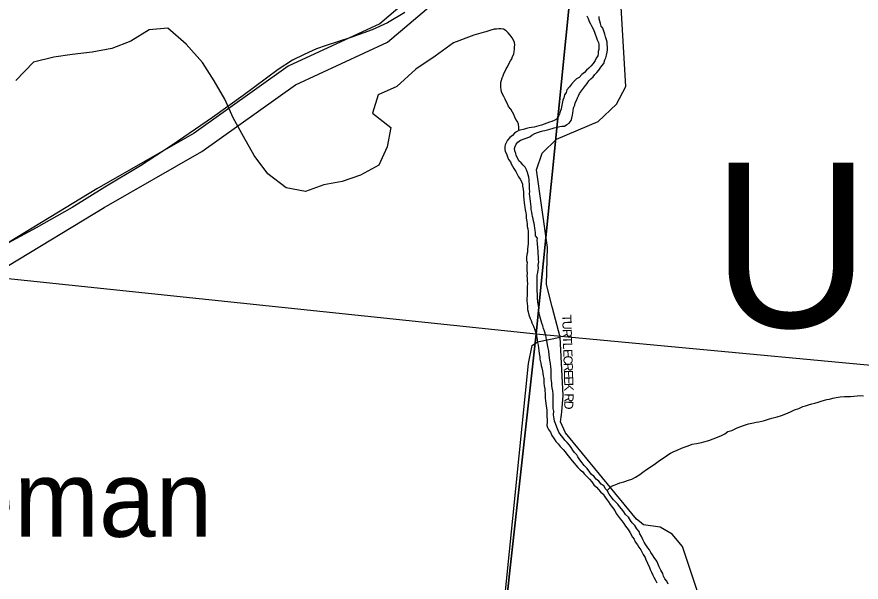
# Model space of a CAD drawing. Extents: x 0 to 34, y -4 to 22.
# Drawn here: x 3.906 to 4.522, y 18.618 to 19.03 of the extents above; entities that cross this region are included whole.
import ezdxf

# ---------------------------------------------------------------- set-up
doc = ezdxf.new("R2010")
doc.units = 0
for name, color, linetype in [('GM_X_City_Street', 7, 'Continuous'), ('GM_X_City_Street_Text', 7, 'Continuous'), ('GM_X_Corporation', 7, 'Continuous'), ('GM_X_County_Road', 7, 'Continuous'), ('GM_X_Minor_River', 7, 'Continuous'), ('GM_X_Rail_Line', 7, 'Continuous'), ('GM_X_Section', 7, 'Continuous'), ('GM_X_Township_Road', 7, 'Continuous'), ('GM_X_Township_Text', 7, 'Continuous'), ('GM_X_Unincorporated_Text', 7, 'Continuous')]:
    doc.layers.add(name, color=color, linetype=linetype)

msp = doc.modelspace()

# ---------------------------------------------------------------- linework, layer by layer
at = {"layer": 'GM_X_City_Street'}
msp.add_lwpolyline([(4.30361, 18.74044), (4.30384, 18.74223), (4.30486, 18.75426), (4.30269, 18.7967)], dxfattribs=at)
at = {"layer": 'GM_X_Corporation'}
msp.add_lwpolyline([(3.90028, 18.84891), (3.97005, 18.89124), (4.04146, 18.932), (4.10968, 18.98061), (4.17685, 19.01173), (4.24489, 19.06965), (4.32583, 19.18677), (4.35455, 19.22188), (4.40569, 19.29705), (4.44231, 19.37455), (4.44713, 19.39206), (4.42391, 19.39206), (4.42052, 19.37907), (4.38533, 19.3024), (4.33505, 19.23202), (4.30739, 19.18845), (4.23841, 19.08244), (4.1712, 19.02523), (4.10434, 18.99426), (4.03585, 18.94545), (3.96469, 18.90484), (3.89508, 18.8626)], dxfattribs=at)
at = {"layer": 'GM_X_County_Road'}
for points in [[(4.30269, 18.7967), (4.29682, 18.81893), (4.29278, 18.83509), (4.29361, 18.86203), (4.28538, 18.9188), (4.28964, 18.93093), (4.29997, 18.94102), (4.33049, 18.95404), (4.34395, 18.96661), (4.35069, 18.9794), (4.34148, 19.13651), (4.33767, 19.16075), (4.33946, 19.17084), (4.3637, 19.18566), (4.38098, 19.19217), (4.40769, 19.19845), (4.42161, 19.2099), (4.43485, 19.23009), (4.47033, 19.29782), (4.51074, 19.39206)], [(4.24504, 18.43619), (4.27961, 18.77764), (4.28221, 18.79071), (4.28627, 18.79333), (4.30269, 18.7967)]]:
    msp.add_lwpolyline(points, dxfattribs=at)
at = {"layer": 'GM_X_Minor_River'}
for points in [[(4.32228, 19.03111), (4.32328, 19.02895), (4.32401, 19.02679), (4.32476, 19.02516), (4.32577, 19.02326), (4.32679, 19.02163), (4.32778, 19.01919), (4.32826, 19.01757), (4.329, 19.01568), (4.32973, 19.01352), (4.33074, 19.01162), (4.33096, 19.01001), (4.3309, 19.00814), (4.33084, 19.00654), (4.33052, 19.00495), (4.33047, 19.00335), (4.33015, 19.00175), (4.32903, 19.00019), (4.32816, 18.99834), (4.32675, 18.99625), (4.32509, 18.99443), (4.32369, 18.99287), (4.32204, 18.99132), (4.32038, 18.98977), (4.31845, 18.98822), (4.31651, 18.98615), (4.3146, 18.98514), (4.31293, 18.98332), (4.31099, 18.98124), (4.30958, 18.97915), (4.30763, 18.97707), (4.30704, 18.97522), (4.3059, 18.97338), (4.3053, 18.97127), (4.3047, 18.96942), (4.30409, 18.96703), (4.30374, 18.96464), (4.30342, 18.96304), (4.30282, 18.96119), (4.30222, 18.95934), (4.30164, 18.95776), (4.29996, 18.95567), (4.29832, 18.95465), (4.29669, 18.9539), (4.29506, 18.95342), (4.2929, 18.95268), (4.291, 18.95194), (4.2891, 18.9512), (4.2872, 18.95072), (4.28558, 18.95024), (4.28369, 18.94976), (4.28181, 18.94955), (4.28019, 18.94934), (4.2783, 18.94886), (4.27668, 18.94838), (4.27263, 18.94743)], [(4.27374, 18.94045), (4.28052, 18.94291), (4.28216, 18.94393), (4.28434, 18.9452), (4.28624, 18.94594), (4.28841, 18.94668), (4.29003, 18.94716), (4.29165, 18.94738), (4.29354, 18.94785), (4.29516, 18.94834), (4.29679, 18.94882), (4.29841, 18.94931), (4.30057, 18.94977), (4.30246, 18.95025), (4.30407, 18.95047), (4.30596, 18.95068), (4.3076, 18.9517), (4.30924, 18.95271), (4.31065, 18.95481), (4.31124, 18.95639), (4.31184, 18.95851), (4.31189, 18.96011), (4.31222, 18.96197), (4.31255, 18.96383), (4.31343, 18.96594), (4.31375, 18.96753), (4.31461, 18.96938), (4.31548, 18.97122), (4.31607, 18.9728), (4.31692, 18.97438), (4.31832, 18.97621), (4.31973, 18.9783), (4.32113, 18.98013), (4.32252, 18.98169), (4.32365, 18.98352), (4.32504, 18.98508), (4.3267, 18.98663), (4.32809, 18.98819), (4.32948, 18.98975), (4.33087, 18.99131), (4.332, 18.99288), (4.33312, 18.99445), (4.33452, 18.99628), (4.33541, 18.99892), (4.336, 19.0005), (4.3366, 19.00236), (4.33694, 19.00448), (4.33727, 19.00634), (4.33734, 19.00848), (4.33712, 19.01009), (4.33691, 19.0117), (4.33643, 19.01358), (4.3357, 19.01574), (4.33523, 19.01762), (4.3345, 19.01978), (4.33376, 19.02194), (4.33275, 19.02358), (4.33227, 19.02546), (4.33179, 19.02708), (4.33131, 19.0287), (4.3311, 19.03058)], [(4.23983, 19.01683), (4.22501, 19.01136), (4.21153, 19.00172), (4.19738, 18.99209), (4.18349, 18.97951), (4.16988, 18.97335), (4.16587, 18.95997), (4.17922, 18.94953), (4.17655, 18.93561), (4.17041, 18.92223), (4.15706, 18.91474), (4.14371, 18.91019), (4.13036, 18.90778), (4.11701, 18.90296), (4.10286, 18.90564), (4.08951, 18.91581), (4.07963, 18.92919), (4.07162, 18.94311), (4.06415, 18.95676), (4.05801, 18.97014), (4.05027, 18.98353), (4.04173, 18.99691), (4.02998, 19.01029), (4.01663, 19.02207), (4.00301, 19.02073), (3.98966, 19.01243), (3.97578, 19.00708), (3.96136, 19.0044), (3.94668, 19.0028), (3.93333, 19.00092), (3.91865, 18.99718), (3.90556, 18.98379)], [(4.27263, 18.94743), (4.27271, 18.94983), (4.27224, 18.95198), (4.2715, 18.95388), (4.27049, 18.95551), (4.26973, 18.95714), (4.26899, 18.95903), (4.26798, 18.96066), (4.26671, 18.96284), (4.26517, 18.96502), (4.26443, 18.96692), (4.26341, 18.96855), (4.26266, 18.97018), (4.26166, 18.97208), (4.26065, 18.97398), (4.2599, 18.97561), (4.25968, 18.97722), (4.25947, 18.97883), (4.25953, 18.98069), (4.25958, 18.9823), (4.25991, 18.98415), (4.2605, 18.98574), (4.26109, 18.98732), (4.26168, 18.98891), (4.26254, 18.99075), (4.2634, 18.99233), (4.26425, 18.9939), (4.26539, 18.99601), (4.26653, 18.99811), (4.26739, 18.99968), (4.26798, 19.00127), (4.26884, 19.00311), (4.26917, 19.00497), (4.26949, 19.00656), (4.26955, 19.00817), (4.2696, 19.00977), (4.26939, 19.01164), (4.26864, 19.01327), (4.26763, 19.0149), (4.26635, 19.01681), (4.2648, 19.01873), (4.26324, 19.02012), (4.2614, 19.02124), (4.25954, 19.02156), (4.25793, 19.02161), (4.25632, 19.0214), (4.25471, 19.02118), (4.25227, 19.02045), (4.25065, 19.01997), (4.24848, 19.01924), (4.24659, 19.01876), (4.24497, 19.01828), (4.24307, 19.0178), (4.24145, 19.01732), (4.23983, 19.01683)], [(4.27263, 18.94743), (4.27099, 18.94641), (4.26935, 18.9454), (4.26795, 18.94384), (4.26603, 18.94229), (4.26436, 18.94047), (4.26351, 18.9389), (4.26264, 18.93705), (4.26232, 18.93546), (4.26227, 18.93386), (4.26274, 18.93198), (4.26349, 18.93035), (4.26422, 18.92819), (4.26496, 18.9263), (4.26652, 18.92465), (4.267, 18.92303), (4.26802, 18.9214), (4.26904, 18.91976), (4.2703, 18.91758), (4.27105, 18.91596), (4.27231, 18.91352), (4.2736, 18.91187), (4.27461, 18.91024), (4.27536, 18.90834), (4.2753, 18.90674), (4.27577, 18.90459), (4.27597, 18.90245), (4.27588, 18.89978), (4.27632, 18.8971), (4.27651, 18.89469), (4.27673, 18.89308), (4.27694, 18.89147), (4.27715, 18.88959)], [(4.2727, 18.92526), (4.27195, 18.92688), (4.27068, 18.92906), (4.27047, 18.93067), (4.26973, 18.93256), (4.26951, 18.93417), (4.26983, 18.93576), (4.27069, 18.93734), (4.27181, 18.93891), (4.27374, 18.94045)], [(4.30797, 18.71981), (4.30616, 18.72174), (4.30487, 18.72338), (4.30359, 18.72502), (4.3018, 18.72748), (4.3003, 18.731), (4.29932, 18.7337), (4.29858, 18.73559), (4.29837, 18.7372), (4.29793, 18.74015), (4.29802, 18.74282), (4.29754, 18.74471), (4.29762, 18.74711), (4.29768, 18.74898), (4.29775, 18.75111), (4.29756, 18.75326), (4.29762, 18.75512), (4.29743, 18.75753), (4.29697, 18.75968), (4.29676, 18.76156), (4.29655, 18.76317), (4.29633, 18.76478), (4.29613, 18.76692), (4.29622, 18.76959), (4.29627, 18.77119), (4.29606, 18.7728), (4.29587, 18.77521), (4.29568, 18.77762), (4.29523, 18.78004), (4.29481, 18.78353), (4.29438, 18.78674), (4.2939, 18.78863), (4.29345, 18.79105), (4.29324, 18.79292), (4.29278, 18.79508), (4.29234, 18.79803), (4.29137, 18.801), (4.29063, 18.80316), (4.29016, 18.80504), (4.28942, 18.80693), (4.28893, 18.80855), (4.28846, 18.81044), (4.28798, 18.81205), (4.28752, 18.8142), (4.2873, 18.81581), (4.28711, 18.81822), (4.2869, 18.81983), (4.28644, 18.82225), (4.28627, 18.8252), (4.2861, 18.82814), (4.2859, 18.83028), (4.28603, 18.83402), (4.28585, 18.8367), (4.28592, 18.83883), (4.28597, 18.84043), (4.28602, 18.84203), (4.28635, 18.84389), (4.28667, 18.84549), (4.28699, 18.84708), (4.2868, 18.84922), (4.28714, 18.85162), (4.28693, 18.85322), (4.287, 18.85536), (4.2868, 18.8575), (4.28659, 18.85911), (4.28641, 18.86179), (4.28625, 18.865), (4.28606, 18.86741), (4.28611, 18.86901), (4.28483, 18.87065), (4.28463, 18.8728), (4.28442, 18.87467), (4.28421, 18.87628), (4.284, 18.87816), (4.28379, 18.87977), (4.28331, 18.88139), (4.28309, 18.883), (4.28261, 18.88461), (4.28239, 18.88622), (4.28218, 18.88783), (4.28171, 18.88972), (4.28151, 18.89186), (4.2813, 18.89374), (4.2811, 18.89561), (4.2809, 18.89776), (4.28069, 18.89963), (4.28048, 18.90124), (4.28053, 18.90284), (4.28033, 18.90499), (4.2804, 18.90685), (4.28045, 18.90846), (4.28023, 18.91006), (4.28002, 18.91167), (4.27981, 18.91328), (4.27933, 18.91517), (4.27885, 18.91679), (4.27811, 18.91868), (4.2771, 18.92058), (4.27581, 18.92222), (4.27426, 18.92387), (4.2727, 18.92526)], [(4.27715, 18.88959), (4.27761, 18.88744), (4.27783, 18.88583), (4.27801, 18.88342), (4.27847, 18.881), (4.27868, 18.87913), (4.27862, 18.87752), (4.2791, 18.87564), (4.2793, 18.87376), (4.2795, 18.87162), (4.27944, 18.86975), (4.27935, 18.86708), (4.27928, 18.86495), (4.27921, 18.86281), (4.27889, 18.86122), (4.27881, 18.85882), (4.27848, 18.85696), (4.27814, 18.85483), (4.27807, 18.8527), (4.27855, 18.85108), (4.27849, 18.84921), (4.27843, 18.84734), (4.27838, 18.84574), (4.27856, 18.84307), (4.2785, 18.84146), (4.27872, 18.83986), (4.27865, 18.83772), (4.27885, 18.83584), (4.27877, 18.83344), (4.2787, 18.83131), (4.27863, 18.82917), (4.27855, 18.82677), (4.27849, 18.8249), (4.27843, 18.82303), (4.27864, 18.82142), (4.27883, 18.81902), (4.27903, 18.81687), (4.27951, 18.81525), (4.27998, 18.8131), (4.28096, 18.8104), (4.28171, 18.80877), (4.28219, 18.80716), (4.28318, 18.80472), (4.28417, 18.80202), (4.2849, 18.79986), (4.28536, 18.79771), (4.28608, 18.79502), (4.28627, 18.79287), (4.28675, 18.79099), (4.28694, 18.78884), (4.28715, 18.78697), (4.28735, 18.78483), (4.2878, 18.78241), (4.28802, 18.7808), (4.28873, 18.77784), (4.28893, 18.77596), (4.28941, 18.77434), (4.28988, 18.77219), (4.29008, 18.77032), (4.29029, 18.76844), (4.29076, 18.76656), (4.29071, 18.76495), (4.29092, 18.76308), (4.29112, 18.7612), (4.29159, 18.75905), (4.29153, 18.75745), (4.29175, 18.75584), (4.29169, 18.75397), (4.2919, 18.75236), (4.2921, 18.75022), (4.29231, 18.74861), (4.29251, 18.74647), (4.29296, 18.74378), (4.2929, 18.74191), (4.29311, 18.7403), (4.29306, 18.7387), (4.29326, 18.73683), (4.29319, 18.73469), (4.29312, 18.73256), (4.2936, 18.73094), (4.29435, 18.72931), (4.29563, 18.7274), (4.29662, 18.72497), (4.29842, 18.72251), (4.29969, 18.7206), (4.30125, 18.71895), (4.30279, 18.71703), (4.30486, 18.71483), (4.30641, 18.71318), (4.3077, 18.71154), (4.30949, 18.70908), (4.31155, 18.70661), (4.31284, 18.70496), (4.31412, 18.70332), (4.31568, 18.70167), (4.31723, 18.70002), (4.31933, 18.69862), (4.32035, 18.69699), (4.32242, 18.69479), (4.32424, 18.69313), (4.32578, 18.69121)], [(4.33709, 18.68498), (4.34014, 18.68809), (4.34204, 18.68884), (4.34449, 18.68983), (4.34639, 18.69057), (4.34909, 18.69129), (4.35261, 18.69252), (4.35505, 18.69324), (4.35778, 18.69476), (4.36078, 18.69654), (4.36299, 18.69834), (4.36573, 18.70013), (4.36902, 18.70243), (4.37231, 18.70473), (4.37422, 18.70601), (4.37669, 18.7078), (4.37943, 18.70959), (4.38135, 18.71086), (4.38327, 18.71214), (4.38518, 18.71315), (4.38817, 18.71439), (4.39116, 18.7159), (4.39387, 18.71689), (4.39604, 18.71762), (4.39902, 18.7186), (4.40226, 18.7193), (4.40576, 18.72), (4.40765, 18.72047), (4.41117, 18.72143), (4.41443, 18.72267), (4.41741, 18.72391), (4.4204, 18.72515), (4.42285, 18.72614), (4.42505, 18.72795), (4.42802, 18.72866), (4.42993, 18.72967), (4.43184, 18.73068), (4.43374, 18.73142), (4.43726, 18.73265), (4.44024, 18.73362), (4.44374, 18.73432), (4.44564, 18.73479), (4.44779, 18.73499), (4.44994, 18.73546), (4.45184, 18.73594), (4.45536, 18.73716), (4.45725, 18.73764), (4.45914, 18.73812), (4.46103, 18.73859), (4.46428, 18.73956), (4.46727, 18.7408), (4.4708, 18.7423), (4.4738, 18.74381), (4.47678, 18.74478), (4.47977, 18.74629), (4.48166, 18.74677), (4.48383, 18.7475), (4.48627, 18.74823), (4.48843, 18.7487), (4.49086, 18.74942), (4.49303, 18.75016), (4.49546, 18.75088), (4.49735, 18.75136), (4.49924, 18.75157), (4.50167, 18.7523), (4.5041, 18.75276), (4.50706, 18.7532), (4.51028, 18.75336), (4.5127, 18.75356), (4.51457, 18.7535), (4.51699, 18.75369), (4.51941, 18.75388), (4.52182, 18.75408), (4.52396, 18.75401)], [(4.38145, 18.61656), (4.38045, 18.61873), (4.37917, 18.62064), (4.37816, 18.62254), (4.37769, 18.62443), (4.37616, 18.62688), (4.37491, 18.62932), (4.37391, 18.63176), (4.37316, 18.63338), (4.37138, 18.63611), (4.3701, 18.63802), (4.36882, 18.63966), (4.36781, 18.64156), (4.36679, 18.64319), (4.36525, 18.64538), (4.36398, 18.64729), (4.36297, 18.64919), (4.36197, 18.65136), (4.36096, 18.65326), (4.36049, 18.65514), (4.35868, 18.65707), (4.35715, 18.65952), (4.35534, 18.66145), (4.35405, 18.66309), (4.35253, 18.66554), (4.35045, 18.66747), (4.34917, 18.66938), (4.34737, 18.67158), (4.34608, 18.67322), (4.3448, 18.67486), (4.34324, 18.67651), (4.34169, 18.67816), (4.33989, 18.68036), (4.33861, 18.68226), (4.33709, 18.68498), (4.33553, 18.68637), (4.33478, 18.68799), (4.33269, 18.68966), (4.33089, 18.69185), (4.32906, 18.69325), (4.32726, 18.69544), (4.32569, 18.69656), (4.3244, 18.6982), (4.32235, 18.70093), (4.32028, 18.70313), (4.31874, 18.70505), (4.3172, 18.70724), (4.31567, 18.70942), (4.31492, 18.71105), (4.31309, 18.7127), (4.31208, 18.71434), (4.3108, 18.71625), (4.30951, 18.71789), (4.30797, 18.71981)], [(4.32578, 18.69121), (4.32731, 18.68902), (4.32914, 18.68737), (4.33069, 18.68572), (4.33224, 18.68406), (4.33405, 18.68214), (4.33533, 18.68023), (4.33661, 18.67859), (4.33789, 18.67668), (4.33917, 18.67477), (4.34097, 18.67258), (4.34251, 18.67039), (4.34351, 18.66822), (4.34505, 18.6663), (4.34659, 18.66439), (4.34761, 18.66275), (4.34916, 18.66084), (4.35043, 18.65893), (4.35223, 18.65647), (4.35375, 18.65402), (4.35553, 18.65102), (4.35681, 18.64938), (4.35755, 18.64749), (4.35909, 18.6453), (4.36011, 18.64367), (4.36165, 18.64175), (4.3624, 18.64012), (4.36341, 18.63822), (4.36468, 18.63605), (4.36516, 18.63443), (4.36618, 18.6328), (4.36666, 18.63118), (4.36768, 18.62954), (4.36841, 18.62738), (4.36942, 18.62548), (4.37042, 18.62331), (4.37117, 18.62169), (4.37217, 18.61952), (4.37318, 18.61762)]]:
    msp.add_lwpolyline(points, dxfattribs=at)
at = {"layer": 'GM_X_Rail_Line'}
msp.add_lwpolyline([(4.18935, 19.03342), (4.17667, 19.02588), (4.16564, 19.02085), (4.15, 19.01516), (4.13196, 19.00948), (4.12507, 19.00696), (4.11589, 19.00292), (4.10747, 18.99866), (4.09709, 18.99177), (4.0714, 18.97297), (4.0491, 18.9569), (4.01969, 18.93678), (3.99662, 18.92159), (3.97059, 18.90601), (3.94677, 18.89119), (3.92043, 18.87655), (3.87298, 18.85096)], dxfattribs=at)
at = {"layer": 'GM_X_Section'}
for points in [[(3.94357, 19.55258), (3.64088, 19.58219), (3.57306, 18.87377), (4.28514, 18.79907), (4.34474, 19.39206), (3.94357, 19.39206)], [(4.34474, 19.39206), (4.28514, 18.79907), (4.99198, 18.73294), (4.99815, 18.79148), (5.05898, 19.39206)], [(3.57306, 18.87377), (4.28514, 18.79907), (4.2059, 18.08556), (3.49733, 18.15618)], [(4.99198, 18.73294), (4.91493, 18.01957), (4.2059, 18.08556), (4.28514, 18.79907)]]:
    msp.add_lwpolyline(points, close=True, dxfattribs=at)
at = {"layer": 'GM_X_Township_Road'}
for points in [[(4.36055, 18.66227), (4.35847, 18.66397), (4.30652, 18.72693), (4.30291, 18.73502), (4.30361, 18.74044)], [(4.38464, 18.43284), (4.36691, 18.44143), (4.35479, 18.45341), (4.34929, 18.46073), (4.35002, 18.47142), (4.35429, 18.48607), (4.36206, 18.50146), (4.38298, 18.53322), (4.39438, 18.55685), (4.40289, 18.58374), (4.40334, 18.60995), (4.39189, 18.64413), (4.38454, 18.65309), (4.37579, 18.65832), (4.36349, 18.65987), (4.36055, 18.66227)]]:
    msp.add_lwpolyline(points, dxfattribs=at)

# ---------------------------------------------------------------- texts
at = {"layer": 'GM_X_City_Street_Text'}
for s, rotation, p in [('T', 271.69434, (4.3042, 18.81317)), ('U', 271.70528, (4.30434, 18.80848)), ('R', 271.7004, (4.30451, 18.80262)), ('T', 271.71406, (4.30467, 18.79734)), ('L', 271.69434, (4.30481, 18.79265)), ('E', 271.70092, (4.30495, 18.78796)), ('C', 271.7004, (4.30509, 18.78326)), ('R', 271.7004, (4.30525, 18.77799)), ('E', 271.69434, (4.3054, 18.77271)), ('E', 271.70092, (4.30554, 18.76802)), ('K', 271.68341, (4.30568, 18.76333)), ('R', 268.90716, (4.30588, 18.75579)), ('D', 267.5731, (4.30578, 18.75055))]:
    msp.add_text(s, height=0.00667, rotation=rotation, dxfattribs=at).set_placement(p)
at = {"layer": 'GM_X_Township_Text'}
msp.add_text('UNION', height=0.12, rotation=0.00001, dxfattribs=at).set_placement((4.41317, 18.80389))
at = {"layer": 'GM_X_Unincorporated_Text'}
msp.add_text('Hageman', height=0.055556, rotation=0.00001, dxfattribs=at).set_placement((3.72684, 18.65118))

doc.saveas('drawing.dxf')
